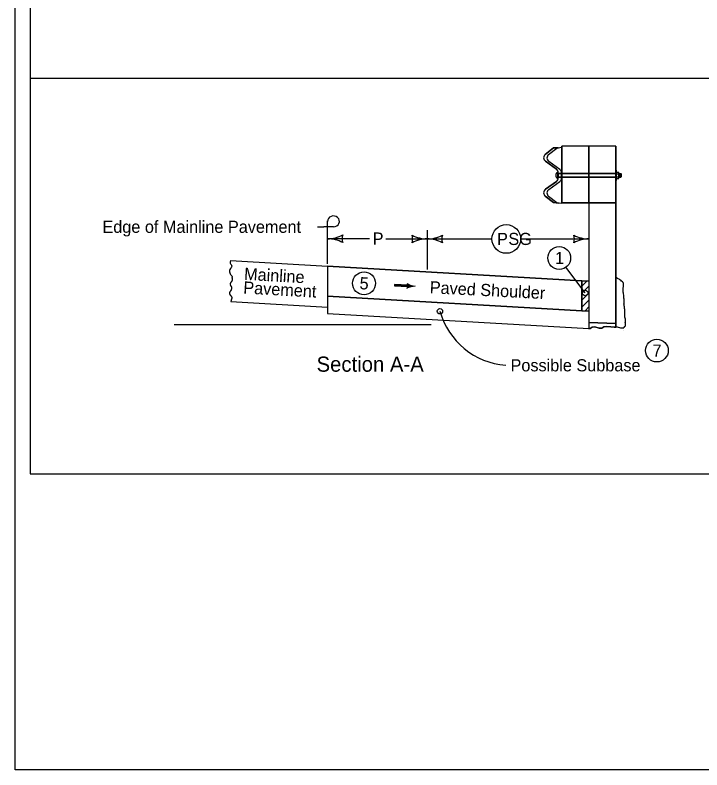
# Model space of a CAD drawing. Extents: x 10133 to 81668, y 7924 to 12229.
# Drawn here: x 10133 to 11037, y 7924 to 8919 of the extents above; entities that cross this region are included whole.
import ezdxf

# ---------------------------------------------------------------- set-up
doc = ezdxf.new("R2010")
doc.units = 0
for name, color, linetype in [('Cell', 7, 'Continuous'), ('dsnTextFinalPlan', 7, 'Continuous'), ('Level 1', 7, 'Continuous'), ('Level 12', 7, 'Continuous'), ('Level 4', 7, 'Continuous'), ('Level 5', 7, 'Continuous'), ('Level 6', 7, 'Continuous'), ('SheetBorder', 7, 'Continuous')]:
    doc.layers.add(name, color=color, linetype=linetype)

msp = doc.modelspace()

# ---------------------------------------------------------------- linework, layer by layer
at = {"layer": 'Cell'}
for p, q in [((10831.21, 8726.07), (10845.72, 8715.65)), ((10845.72, 8699.58), (10831.21, 8689.16))]:
    msp.add_line(p, q, dxfattribs=at)
for points in [[(10835.46, 8734.97), (10835.45, 8734.96), (10846.22, 8743.37), (10848.11, 8743.7), (10841.78, 8743.59), (10831.02, 8735.19)], [(10888.5, 8710.28), (10888.5, 8745.95), (10852.96, 8745.95), (10852.96, 8710.28), (10852.96, 8710.28), (10888.5, 8710.28)], [(10924.05, 8710.28), (10924.05, 8714.27), (10924.05, 8745.95), (10888.5, 8745.95), (10888.5, 8710.28), (10924.05, 8710.28)], [(10850.16, 8715.44), (10850.19, 8715.42), (10835.63, 8725.87), (10835.66, 8725.85)], [(10848.11, 8711.02), (10848.11, 8709.94), (10852.56, 8709.94), (10852.56, 8710.8), (10852.56, 8710.8)], [(10852.56, 8703.99), (10852.56, 8703.99), (10852.56, 8705.28), (10848.12, 8705.28), (10848.12, 8704.21), (10848.12, 8705.28), (10848.11, 8705.28), (10848.11, 8704.21)], [(10852.96, 8709.94), (10852.96, 8705.28), (10852.96, 8705.28), (10888.5, 8705.28), (10888.5, 8709.94), (10852.96, 8709.94), (10852.96, 8709.94)], [(10852.96, 8704.94), (10852.96, 8671.3), (10888.5, 8671.3), (10888.5, 8704.94), (10852.96, 8704.94)], [(10924.05, 8705.28), (10924.05, 8709.94), (10888.5, 8709.94), (10888.5, 8705.28), (10924.05, 8705.28)], [(10924.05, 8671.3), (10924.05, 8700.94), (10924.05, 8704.94), (10888.5, 8704.94), (10888.5, 8671.3), (10924.05, 8671.3)], [(10835.66, 8688.95), (10835.63, 8688.93), (10850.19, 8699.38), (10850.16, 8699.36)], [(10831.02, 8680.04), (10841.78, 8671.65), (10848.88, 8670.96), (10846.22, 8671.43), (10835.45, 8679.84), (10835.46, 8679.82)], [(10924.05, 8512.36), (10924.05, 8671.3), (10888.5, 8671.3), (10888.5, 8568.33), (10888.5, 8561.64), (10888.5, 8561.64), (10888.5, 8561.64), (10888.5, 8552.41), (10888.5, 8552.41), (10888.5, 8552.41), (10888.5, 8543.27), (10888.5, 8543.27), (10888.5, 8543.27), (10888.5, 8536.34), (10888.5, 8513.52), (10924.05, 8512.36)], [(10924.05, 8512.36), (10888.5, 8513.52), (10888.5, 8505.49), (10890.14, 8505.72), (10892.9, 8507.31), (10896.18, 8507.84), (10901.8, 8506.25), (10905.51, 8506.04), (10908.16, 8507.84), (10911.23, 8508.47), (10917.49, 8507.73), (10921.73, 8507.31), (10924.05, 8507.31), (10924.05, 8512.36)]]:
    msp.add_lwpolyline(points, dxfattribs=at)
msp.add_lwpolyline([(10852.56, 8709.94), (10848.11, 8709.94), (10848.11, 8706.48), (10848.12, 8707.62), (10848.12, 8705.28), (10852.56, 8705.28)], close=True, dxfattribs=at)
for centre, start, end in [((10834.49, 8730.7), 127.75002, 234.69086), ((10838.94, 8730.48), 127.75002, 234.69086), ((10842.44, 8711.02), 0, 54.69099), ((10846.88, 8710.8), 0, 54.69099), ((10842.44, 8704.21), 305.30901, 0), ((10846.88, 8703.99), 305.30901, 0), ((10834.49, 8684.53), 125.30914, 232.24998), ((10838.94, 8684.31), 125.30914, 232.24998)]:
    msp.add_arc(centre, 5.68, start, end, dxfattribs=at)
at = {"layer": 'dsnTextFinalPlan'}
for p, q in [((10831.02, 8735.19), (10841.78, 8743.59)), ((10841.78, 8743.59), (10848.11, 8743.7)), ((10846.22, 8743.37), (10852.56, 8744.49)), ((10924.05, 8745.95), (10852.96, 8745.95)), ((10852.96, 8671.3), (10852.96, 8745.95)), ((10888.5, 8671.3), (10888.5, 8745.95)), ((10924.05, 8745.95), (10924.05, 8507.31)), ((10835.45, 8734.96), (10846.22, 8743.37)), ((10845.72, 8715.65), (10831.21, 8726.07)), ((10850.19, 8715.42), (10835.63, 8725.87)), ((10924.05, 8714.25), (10924.73, 8714.25)), ((10924.73, 8700.91), (10924.73, 8714.25)), ((10847.34, 8703.55), (10847.34, 8711.63)), ((10847.34, 8709.94), (10852.77, 8709.94)), ((10847.34, 8705.28), (10852.96, 8705.28)), ((10848.12, 8704.21), (10848.11, 8711.02)), ((10848.11, 8704.21), (10848.12, 8707.62)), ((10848.12, 8707.62), (10848.12, 8704.21)), ((10848.29, 8709.94), (10852.96, 8709.94)), ((10852.56, 8707.4), (10852.56, 8710.8)), ((10852.56, 8703.99), (10852.56, 8707.4)), ((10852.56, 8707.4), (10852.56, 8703.99)), ((10852.95, 8704.94), (10924.05, 8704.94)), ((10852.96, 8710.28), (10924.05, 8710.28)), ((10852.96, 8709.94), (10924.05, 8709.94)), ((10852.96, 8705.28), (10924.05, 8705.28)), ((10924.73, 8711.62), (10927.7, 8711.62)), ((10924.73, 8709.6), (10927.7, 8709.6)), ((10924.73, 8705.56), (10927.7, 8705.56)), ((10928.06, 8704.55), (10928.06, 8710.61)), ((10928.06, 8709.91), (10930.43, 8709.91)), ((10928.06, 8705.25), (10930.43, 8705.25)), ((10928.95, 8709.91), (10928.95, 8705.25)), ((10929.69, 8709.91), (10929.69, 8705.25)), ((10930.43, 8709.91), (10930.88, 8709.38)), ((10930.43, 8709.91), (10930.43, 8705.25)), ((10930.88, 8705.78), (10930.43, 8705.25)), ((10930.88, 8709.38), (10930.88, 8705.78)), ((10831.21, 8689.16), (10845.72, 8699.58)), ((10835.63, 8688.93), (10850.19, 8699.38)), ((10924.05, 8700.91), (10924.73, 8700.91)), ((10924.73, 8703.54), (10927.7, 8703.54)), ((10841.78, 8671.65), (10831.02, 8680.04)), ((10846.22, 8671.43), (10835.45, 8679.84)), ((10848.88, 8670.96), (10841.78, 8671.65)), ((10852.56, 8670.31), (10846.22, 8671.43)), ((10888.5, 8671.3), (10852.96, 8671.3)), ((10888.5, 8671.3), (10888.5, 8504.77)), ((10416.5, 8595.25), (10544.11, 8587.82)), ((10544.11, 8587.82), (10544.11, 8533.81)), ((10544.11, 8587.82), (10879.25, 8568.34)), ((10879.25, 8568.34), (10544.11, 8587.82)), ((10544.11, 8587.82), (10544.11, 8548.23)), ((10879.25, 8561.59), (10885.99, 8568.34)), ((10879.25, 8561.59), (10885.99, 8568.34)), ((10879.25, 8561.59), (10885.99, 8568.34)), ((10879.25, 8561.59), (10885.99, 8568.34)), ((10879.25, 8568.34), (10888.49, 8568.34)), ((10879.25, 8568.34), (10879.25, 8528.91)), ((10879.25, 8528.91), (10879.25, 8568.34)), ((10879.25, 8552.41), (10888.49, 8561.64)), ((10879.25, 8552.41), (10888.49, 8561.64)), ((10879.25, 8552.41), (10888.49, 8561.64)), ((10879.25, 8552.41), (10888.49, 8561.64)), ((10934.1, 8561.57), (10934.1, 8561.57)), ((10879.25, 8528.91), (10544.11, 8548.23)), ((10544.11, 8548.23), (10879.25, 8528.91)), ((10879.25, 8543.18), (10888.49, 8552.42)), ((10879.25, 8543.18), (10888.49, 8552.42)), ((10879.25, 8543.18), (10888.49, 8552.42)), ((10879.25, 8543.18), (10888.49, 8552.42)), ((10416.68, 8541.22), (10544.11, 8533.81)), ((10879.25, 8533.95), (10888.49, 8543.19)), ((10544.11, 8533.81), (10544.11, 8525.39)), ((10544.11, 8525.39), (10888.5, 8505.53)), ((10879.25, 8528.91), (10888.49, 8528.91)), ((10883.35, 8528.91), (10888.49, 8534.05)), ((10342.06, 8510.98), (10680.56, 8510.98)), ((10934.45, 8502.5), (10934.45, 8502.5))]:
    msp.add_line(p, q, dxfattribs=at)
for points in [[(10928.05, 8704.87), (10928, 8705.14), (10927.96, 8705.31), (10927.87, 8705.47), (10927.75, 8705.56), (10927.83, 8705.66), (10927.91, 8705.88), (10927.97, 8706.19), (10928.05, 8706.94), (10928.05, 8704.87), (10928.03, 8705.01), (10927.99, 8705.23), (10927.91, 8705.44), (10927.79, 8705.55), (10927.83, 8705.64), (10927.89, 8705.79), (10927.99, 8706.29), (10928.03, 8706.67), (10928.03, 8705.06), (10928, 8705.18), (10927.96, 8705.35), (10927.83, 8705.55), (10927.88, 8705.72), (10927.96, 8706.05), (10928.02, 8706.38), (10928.01, 8705.22), (10927.97, 8705.35), (10927.86, 8705.54), (10927.9, 8705.76), (10927.96, 8706.01), (10927.99, 8706.19), (10927.99, 8705.32), (10927.93, 8705.43), (10927.88, 8705.54), (10927.97, 8706), (10927.97, 8705.4), (10927.9, 8705.54), (10927.95, 8705.83), (10927.95, 8705.48), (10927.92, 8705.55), (10927.93, 8705.65), (10927.93, 8705.57)], [(10927.76, 8709.6), (10927.83, 8709.65), (10927.91, 8709.75), (10927.99, 8709.97), (10928.05, 8710.26), (10928.05, 8708.31), (10927.99, 8708.82), (10927.94, 8709.19), (10927.82, 8709.52), (10927.76, 8709.6), (10927.82, 8709.61), (10927.92, 8709.76), (10928.01, 8709.98), (10928.03, 8710.14), (10928.03, 8708.6), (10927.96, 8709.09), (10927.9, 8709.36), (10927.8, 8709.58), (10927.83, 8709.59), (10927.97, 8709.81), (10928.01, 8709.96), (10928.01, 8708.86), (10927.82, 8709.57), (10927.99, 8709.85), (10927.99, 8708.99), (10927.85, 8709.56), (10927.97, 8709.78), (10927.98, 8709.14), (10927.87, 8709.54), (10927.96, 8709.71), (10927.96, 8709.3), (10927.89, 8709.53), (10927.94, 8709.64), (10927.94, 8709.44), (10927.91, 8709.51), (10927.92, 8709.56)], [(10934.57, 8537.73), (10934.51, 8537.46), (10934.51, 8537.26), (10934.51, 8537.06), (10934.51, 8536.87), (10934.51, 8536.67), (10934.51, 8536.48), (10934.51, 8536.19), (10934.51, 8535.99), (10934.61, 8535.7), (10934.71, 8535.4), (10934.9, 8535.21), (10934.9, 8535.01), (10935, 8534.82), (10935, 8534.62), (10935, 8534.43), (10935.1, 8534.33), (10935.1, 8534.13), (10935.1, 8533.94), (10935.1, 8533.74), (10935.1, 8533.55), (10935.1, 8533.35), (10935.1, 8533.06), (10935.1, 8532.77), (10935.1, 8532.57), (10935.1, 8532.28), (10935.1, 8532.08), (10935.1, 8531.89), (10935.2, 8531.79), (10935.2, 8531.59), (10935.2, 8531.4), (10935.2, 8531.2), (10935.2, 8531.01), (10935.2, 8530.81), (10935.2, 8530.62), (10935.2, 8530.42), (10935.2, 8530.23), (10935.2, 8530.03), (10935.2, 8529.83), (10935.2, 8529.64), (10935.2, 8529.44), (10935.2, 8529.25), (10935.2, 8529.05), (10935.2, 8528.86), (10935.2, 8528.66), (10935.2, 8528.47), (10935.2, 8528.27), (10935.29, 8528.17), (10935.29, 8527.98), (10935.29, 8527.78), (10935.39, 8527.68), (10935.39, 8527.49), (10935.39, 8527.29), (10935.49, 8527.2), (10935.49, 8527), (10935.49, 8526.81), (10935.49, 8526.61), (10935.49, 8526.32), (10935.59, 8526.02), (10935.59, 8525.83), (10935.59, 8525.63), (10935.59, 8525.44), (10935.59, 8525.24), (10935.59, 8525.05), (10935.59, 8524.85), (10935.59, 8524.66), (10935.59, 8524.46), (10935.59, 8524.27), (10935.59, 8524.07), (10935.59, 8523.87), (10935.59, 8523.68), (10935.59, 8523.48), (10935.59, 8523.29), (10935.59, 8523.09), (10935.59, 8522.9), (10935.59, 8522.7), (10935.59, 8522.51), (10935.59, 8522.31), (10935.59, 8522.12), (10935.59, 8521.92), (10935.59, 8521.72), (10935.59, 8521.53), (10935.59, 8521.33), (10935.59, 8521.14), (10935.59, 8520.94), (10935.59, 8520.75), (10935.59, 8520.55), (10935.59, 8520.36), (10935.68, 8520.26), (10935.68, 8519.97), (10935.68, 8519.77), (10935.78, 8519.58), (10935.88, 8519.28), (10935.88, 8519.09), (10935.98, 8518.99), (10935.98, 8518.79), (10936.07, 8518.7), (10936.17, 8518.6), (10936.17, 8518.4), (10936.17, 8518.21), (10936.17, 8518.01), (10936.27, 8517.91), (10936.27, 8517.72), (10936.27, 8517.52), (10936.27, 8517.33), (10936.27, 8517.13), (10936.27, 8516.94), (10936.27, 8516.74), (10936.27, 8516.55), (10936.27, 8516.35), (10936.27, 8516.16), (10936.27, 8515.96), (10936.27, 8515.76), (10936.27, 8515.57), (10936.27, 8515.37), (10936.27, 8515.18), (10936.27, 8514.98), (10936.27, 8514.79), (10936.27, 8514.59), (10936.27, 8514.4), (10936.27, 8514.2), (10936.27, 8514.01), (10936.27, 8513.81), (10936.27, 8513.62), (10936.27, 8513.42), (10936.27, 8513.22), (10936.27, 8513.03), (10936.27, 8513.03), (10936.27, 8513.32), (10936.27, 8513.52), (10936.27, 8513.71), (10936.27, 8513.52), (10936.27, 8513.32), (10936.27, 8513.13), (10936.27, 8512.93), (10936.27, 8512.74), (10936.27, 8512.54), (10936.27, 8512.35), (10936.27, 8512.15), (10936.27, 8511.95), (10936.27, 8511.76), (10936.27, 8511.56), (10936.27, 8511.37), (10936.27, 8511.17), (10936.27, 8510.98), (10936.27, 8510.78), (10936.17, 8510.68), (10936.17, 8510.49), (10936.17, 8510.29), (10936.17, 8510.1), (10936.17, 8509.9), (10936.17, 8509.71), (10936.17, 8509.51), (10936.17, 8509.32), (10936.17, 8509.12), (10936.17, 8508.93), (10936.17, 8508.73), (10936.07, 8508.63), (10935.98, 8508.44), (10935.88, 8508.34), (10935.78, 8508.24), (10935.68, 8508.14), (10935.49, 8508.05), (10935.29, 8508.05), (10935.2, 8507.95), (10935.1, 8507.85), (10935, 8507.75), (10934.8, 8507.66), (10934.71, 8507.56), (10934.71, 8507.36), (10934.61, 8507.26), (10934.61, 8507.07), (10934.61, 8506.87), (10934.61, 8506.68), (10934.61, 8506.48), (10934.61, 8506.39), (10934.61, 8506.58)], [(10934.57, 8506.26), (10930.42, 8506.14), (10926.28, 8507.31), (10921.73, 8507.31), (10917.49, 8507.73), (10911.23, 8508.47), (10908.16, 8507.84), (10905.51, 8506.04), (10901.8, 8506.25), (10896.18, 8507.84), (10892.9, 8507.31), (10890.14, 8505.72), (10888.5, 8505.49)]]:
    msp.add_lwpolyline(points, dxfattribs=at)
msp.add_circle((10592.23, 8565.25), 15, dxfattribs=at)
for centre, radius, start, end in [((10834.49, 8730.7), 5.68, 127.75002, 234.69086), ((10838.94, 8730.48), 5.68, 127.75002, 234.69086), ((10842.44, 8711.02), 5.68, 360, 54.69099), ((10846.88, 8710.8), 5.68, 360, 54.69099), ((10849.42, 8707.6), 4.54, 117.20289, 242.8461), ((10842.44, 8704.21), 5.68, 305.30901, 0), ((10846.88, 8703.99), 5.68, 305.30901, 0), ((10834.49, 8684.53), 5.68, 125.30914, 232.24998), ((10838.94, 8684.31), 5.68, 125.30914, 232.24998)]:
    msp.add_arc(centre, radius, start, end, dxfattribs=at)
for centre in [(10927.7, 8710.61), (10927.7, 8704.55)]:
    msp.add_ellipse(centre, major_axis=(0, -1.01), ratio=0.362258, start_param=6.283156, end_param=9.424748, dxfattribs=at)
for points in [[(10416.5, 8595.25), (10415.99, 8591.64), (10417.03, 8590.14), (10417.9, 8587.84), (10417.29, 8585.78), (10415.39, 8583.41), (10414.87, 8581.51), (10415.39, 8579.21), (10416.25, 8576.83), (10417.29, 8576.12), (10418.68, 8573.59), (10418.67, 8572.75)], [(10416.71, 8555.64), (10416.92, 8555.88), (10417.12, 8556.14), (10417.47, 8556.7), (10417.75, 8557.29), (10417.87, 8557.6), (10417.97, 8557.92), (10418.1, 8558.53), (10418.15, 8559.15), (10418.1, 8559.74), (10418.04, 8560.02), (10418, 8560.15), (10417.96, 8560.28), (10417.75, 8560.66), (10417.47, 8561.02), (10417.17, 8561.39), (10416.92, 8561.79), (10416.78, 8562.07), (10416.64, 8562.36), (10416.38, 8562.93), (10416.18, 8563.5), (10416.1, 8563.79), (10416.05, 8564.09), (10416.04, 8564.21), (10416.04, 8564.34), (10416.19, 8565.12), (10416.4, 8565.63), (10416.66, 8566.14), (10417.1, 8566.78), (10417.62, 8567.33), (10418.13, 8567.87), (10418.37, 8568.18), (10418.56, 8568.52), (10418.77, 8568.99), (10418.93, 8569.47), (10419.03, 8569.94), (10419.06, 8570.18), (10419.08, 8570.3), (10419.08, 8570.42), (10419.04, 8570.93), (10418.89, 8571.44), (10418.84, 8571.57), (10418.78, 8571.7), (10418.73, 8571.83), (10418.71, 8571.96), (10418.67, 8572.75)], [(10934.57, 8537.73), (10934.89, 8540.63), (10934.67, 8545.5), (10934.23, 8551.25), (10933.56, 8555.67), (10933.78, 8558.99), (10934.23, 8563.19), (10933.56, 8566.28), (10931.35, 8568.27), (10929.36, 8570.04), (10927.15, 8571.15), (10924.94, 8572.47), (10924.06, 8573.14)], [(10416.71, 8555.64), (10416.49, 8555.4), (10416.25, 8555.16), (10416.01, 8554.92), (10415.83, 8554.65), (10415.69, 8554.37), (10415.55, 8554.09), (10415.29, 8553.51), (10415.18, 8553.23), (10415.08, 8552.94), (10415.01, 8552.65), (10414.98, 8552.5), (10414.96, 8552.36), (10414.97, 8551.84), (10415.1, 8551.33), (10415.31, 8550.81), (10415.57, 8550.3), (10416.01, 8549.66), (10416.53, 8549.12), (10417.05, 8548.57), (10417.28, 8548.26), (10417.48, 8547.92), (10417.88, 8546.98), (10417.99, 8546.5), (10418, 8546.02), (10417.96, 8545.73), (10417.91, 8545.44), (10417.86, 8545.16), (10417.79, 8544.87), (10417.48, 8543.72), (10417.3, 8543.11), (10417.1, 8542.51), (10416.88, 8541.92), (10416.75, 8541.64), (10416.61, 8541.35), (10416.53, 8541.23)]]:
    msp.add_spline(points, degree=3, dxfattribs=at)
at = {"layer": 'Level 1'}
for p, q in [((10152.18, 9924.36), (10152.18, 8314.36)), ((10152.18, 8314.36), (13247.87, 8314.36))]:
    msp.add_line(p, q, dxfattribs=at)
at = {"layer": 'Level 12'}
for centre, radius in [((10849.44, 8598.63), 15), ((10592.23, 8565.25), 15), ((10883.56, 8552.51), 3.58), ((10978.03, 8476.61), 15)]:
    msp.add_circle(centre, radius, dxfattribs=at)
at = {"layer": 'Level 4'}
for p, q in [((12307.76, 8835.36), (10152.18, 8835.36)), ((10883.56, 8552.51), (10858.18, 8586.44))]:
    msp.add_line(p, q, dxfattribs=at)
msp.add_circle((10692.27, 8528.41), 3.54, dxfattribs=at)
at = {"layer": 'Level 5'}
for p, q in [((10675.49, 8635.35), (10675.49, 8583.33)), ((10599.61, 8623.96), (10544.13, 8623.96)), ((10620.73, 8623.74), (10675.49, 8623.74)), ((10675.49, 8623.74), (10760.66, 8623.74)), ((10798.53, 8623.74), (10888.5, 8623.74))]:
    msp.add_line(p, q, dxfattribs=at)
msp.add_circle((10779.6, 8623.74), 18.93, dxfattribs=at)
for centre, radius, start, end in [((10544.13, 8666.46), 42.5, 270, 298.07249), ((10579.77, 8623.96), 16.42, 162.26665, 197.73335), ((10639.85, 8623.74), 16.42, 342.26665, 17.73335), ((10675.49, 8666.24), 42.5, 241.92751, 270), ((10675.49, 8666.24), 42.5, 270, 298.07249), ((10711.12, 8623.74), 16.42, 162.26665, 197.73335), ((10852.87, 8623.74), 16.42, 342.26665, 17.73335), ((10888.5, 8666.24), 42.5, 241.92751, 270), ((10544.13, 8581.46), 42.5, 61.92751, 90), ((10675.49, 8581.24), 42.5, 90, 118.07249), ((10675.49, 8581.24), 42.5, 61.92751, 90), ((10888.5, 8581.24), 42.5, 90, 118.07249), ((10786.43, 8554.7), 97.76, 195.59781, 265.55799)]:
    msp.add_arc(centre, radius, start, end, dxfattribs=at)
at = {"layer": 'Level 6'}
for p, q in [((10544.11, 8626.9), (10544.11, 8647.76)), ((10530.74, 8639.75), (10539.43, 8639.75)), ((10551.92, 8639.75), (10539.43, 8639.75)), ((10544.11, 8590.97), (10544.11, 8626.9)), ((10650.5, 8561.86), (10632.29, 8562.91)), ((10650.39, 8560.92), (10650.39, 8560.92)), ((10650.51, 8562.87), (10650.51, 8562.87))]:
    msp.add_line(p, q, dxfattribs=at)
for points in [[(10650.52, 8562.8), (10632.36, 8563.85), (10632.23, 8561.97), (10650.39, 8560.92), (10650.45, 8562.54), (10632.58, 8563.63), (10632.52, 8562.13), (10650.01, 8561.19), (10650.13, 8562.31), (10632.81, 8563.37), (10632.79, 8562.37), (10649.8, 8561.39), (10649.89, 8562.09), (10633, 8563.15), (10632.98, 8562.59), (10649.59, 8561.65)], [(10650.12, 8564.06), (10650.81, 8562.89), (10650.79, 8561.25), (10650.03, 8559.85), (10652.79, 8560.71), (10655.98, 8561.36), (10656.88, 8561.5), (10654.64, 8562.05), (10651.41, 8563.27), (10650.47, 8563.81), (10650.59, 8560.3), (10655.54, 8561.51), (10650.9, 8563.1), (10650.91, 8560.67), (10654.31, 8561.61), (10651.31, 8562.47), (10651.08, 8561.08), (10653.24, 8561.58), (10651.65, 8562.09), (10651.51, 8561.43), (10652.3, 8561.6)]]:
    msp.add_lwpolyline(points, dxfattribs=at)
for centre, major_axis, start_param, end_param in [((10551.92, 8646.89), (-7.81, 0), 1.570796, 6.283185), ((10646.73, 8562.08), (3.88, 0), 5.202895, 7.237436), ((10661.79, 8581.5), (-22.17, 0), 0.954258, 1.478381), ((10659, 8541.08), (22.17, 0), 1.537172, 2.061295)]:
    msp.add_ellipse(centre, major_axis=major_axis, ratio=0.913811, start_param=start_param, end_param=end_param, dxfattribs=at)
at = {"layer": 'SheetBorder'}
msp.add_lwpolyline([(10132.52, 9944.02), (13267.53, 9944.02), (13267.53, 7924.02), (10132.52, 7924.02)], close=True, dxfattribs=at)

# ---------------------------------------------------------------- texts
at = {"layer": 'Level 12'}
for s, p in [('1', (10843.82, 8590.63)), ('7', (10972.32, 8468.61))]:
    msp.add_text(s, height=16, dxfattribs=at).set_placement(p)
msp.add_text('5', height=16, rotation=356.69973, dxfattribs=at).set_placement((10586.01, 8557.6))
at = {"layer": 'Level 5'}
for s, p in [('P', (10603.61, 8616.22)), ('P', (10767.47, 8615.74)), ('SG', (10782.38, 8615.74))]:
    msp.add_text(s, height=16, dxfattribs=at).set_placement(p)
at = {"layer": 'Level 6'}
for s, height, p in [('Edge of Mainline Pavement', 16, (10247.58, 8631.75)), ('Section A-A', 20, (10529.69, 8448.73)), ('Possible Subbase', 16, (10785.21, 8449.23))]:
    msp.add_text(s, height=height, dxfattribs=at).set_placement(p)
for s, rotation, p in [('Mainline', 356.73462, (10433.87, 8569.9)), ('Pavement', 356.73462, (10432.84, 8551.93)), ('Paved Shoulder ', 357.0678, (10678.51, 8552.23))]:
    msp.add_text(s, height=16, rotation=rotation, dxfattribs=at).set_placement(p)

doc.saveas('drawing.dxf')
